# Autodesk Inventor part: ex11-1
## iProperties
Author: Administrator
Created: 2001-09
Part Number: ex11-1
Document SubType Name: Modeling
Designer: Administrator
Control State: 0
Master: False
Checked Out: False
PropertySet Name: Design Tracking Control
Length Units: 11269
Angle Units: 11279
Time Units: 11290
Mass Units: 11283
Shininess: 3
Angle Display Precision: 2
Document Length Units: 11269
Document Angle Units: 11283
Document Time Units: 11279
Document Mass Units: 11290
Document Length Units Precision: 3
Document Angle Units Precision: 2
Compacted: False
PropertySet Name: _Private Model Information
Density: 0.0
Volumn: 0.0
Area: 0.0
PropertySet Name: Model Information
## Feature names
1. Extrusion1
2. Extrusion2
3. Hole1
4. Fillet1
5. Hole2
6. Rectangular Pattern1
7. Fillet2
8. Fillet3
